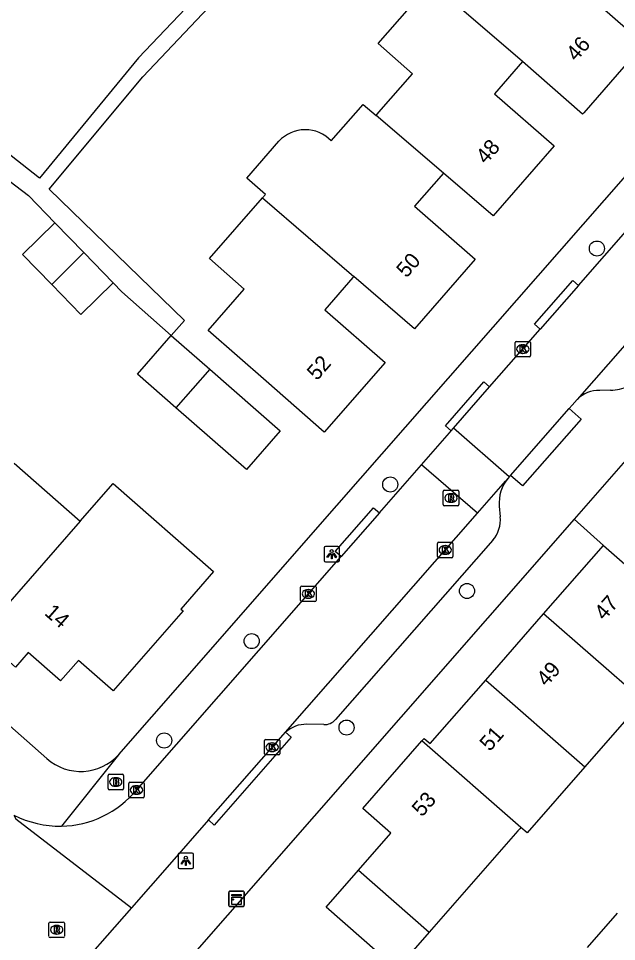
# Model space of a CAD drawing. Extents: x 158474 to 159560, y 388525 to 389605.
# Drawn here: x 158756.5 to 158795.3, y 388856.6 to 388916.5 of the extents above; entities that cross this region are included whole.
import ezdxf

# ---------------------------------------------------------------- set-up
doc = ezdxf.new("R2010")
doc.units = 0
for name, color, linetype in [('IMGEO_Boom', 7, 'Continuous'), ('IMGEO_Brandkraan', 7, 'Continuous'), ('IMGEO_Kast', 7, 'Continuous'), ('IMGEO_Kolk', 7, 'Continuous'), ('IMGEO_Lichtpunt', 7, 'Continuous'), ('IMGEO_Pand', 7, 'Continuous'), ('IMGEO_Pand_nummerreeks', 7, 'Continuous'), ('IMGEO_Rijbaan_lokaal_open', 7, 'Continuous'), ('IMGEO_Rioolput', 7, 'Continuous'), ('IMGEO_Voetpad_open', 7, 'Continuous')]:
    doc.layers.add(name, color=color, linetype=linetype)

msp = doc.modelspace()

# ---------------------------------------------------------------- linework, layer by layer
at = {"layer": 'IMGEO_Boom'}
for centre in [(158793.979, 388901.55), (158780.575, 388886.259), (158785.553, 388879.36), (158771.587, 388876.112), (158777.739, 388870.505), (158765.91, 388869.67)]:
    msp.add_circle(centre, 0.489, dxfattribs=at)
at = {"layer": 'IMGEO_Brandkraan'}
for p, q in [((158762.27, 388866.554), (158762.27, 388867.406)), ((158762.345, 388867.48), (158763.197, 388867.48)), ((158762.758, 388867.26), (158762.783, 388867.26)), ((158763.271, 388867.406), (158763.271, 388866.554)), ((158762.781, 388866.7), (158762.756, 388866.7)), ((158763.197, 388866.48), (158762.345, 388866.48))]:
    msp.add_line(p, q, dxfattribs=at)
for points in [[(158762.27, 388866.554), (158762.27, 388867.406)], [(158762.345, 388867.48), (158763.197, 388867.48)], [(158763.271, 388867.406), (158763.271, 388866.554)], [(158762.618, 388867.18), (158762.618, 388866.78), (158762.831, 388866.78)], [(158762.849, 388867.18), (158762.618, 388867.18)], [(158762.797, 388867.099), (158762.743, 388867.099), (158762.743, 388867.023)], [(158762.743, 388867.023), (158762.796, 388867.023)], [(158762.805, 388866.947), (158762.743, 388866.947), (158762.743, 388866.866)], [(158762.743, 388866.866), (158762.805, 388866.866)], [(158763.197, 388866.48), (158762.345, 388866.48)]]:
    msp.add_lwpolyline(points, dxfattribs=at)
for centre, radius, start, end in [((158762.347, 388867.404), 0.0765, 91.55205, 178.44795), ((158762.347, 388867.404), 0.0765, 91.55205, 178.44795), ((158763.195, 388867.404), 0.0765, 1.55205, 88.44795), ((158763.195, 388867.404), 0.0765, 1.55205, 88.44795), ((158762.798, 388867.061), 0.0379, 267.82845, 90.93552), ((158762.806, 388866.906), 0.0404, 269.87594, 90.50774), ((158762.837, 388867.031), 0.251, 268.66757, 293.53466), ((158762.853, 388867.035), 0.145, 59.4692, 91.53667), ((158762.878, 388867.082), 0.0922, 285.51372, 58.15012), ((158762.883, 388866.89), 0.105, 301.31148, 78.98903), ((158762.347, 388866.556), 0.0765, 181.55205, 268.44795), ((158762.347, 388866.556), 0.0765, 181.55205, 268.44795), ((158763.195, 388866.556), 0.0765, 271.55205, 358.44795), ((158763.195, 388866.556), 0.0765, 271.55205, 358.44795)]:
    msp.add_arc(centre, radius, start, end, dxfattribs=at)
for centre, major_axis, ratio, start_param, end_param in [((158762.757, 388866.98), (-0.387, 0.002), 0.722429, 4.712389, 7.853982), ((158762.782, 388866.98), (-0.39, 0.002), 0.717154, 1.570796, 4.712389)]:
    msp.add_ellipse(centre, major_axis=major_axis, ratio=ratio, start_param=start_param, end_param=end_param, dxfattribs=at)
at = {"layer": 'IMGEO_Kast'}
for p, q in [((158770.1, 388858.98), (158770.1, 388859.821)), ((158770.1, 388859.821), (158770.1, 388858.98)), ((158770.175, 388859.905), (158771.016, 388859.905)), ((158771.016, 388859.905), (158770.175, 388859.905)), ((158771.1, 388859.83), (158771.1, 388858.989)), ((158771.1, 388858.989), (158771.1, 388859.83)), ((158771.025, 388858.905), (158770.184, 388858.905)), ((158770.184, 388858.905), (158771.025, 388858.905))]:
    msp.add_line(p, q, dxfattribs=at)
for points in [[(158770.295, 388859.695), (158770.895, 388859.695), (158770.895, 388859.61), (158770.295, 388859.61), (158770.295, 388859.695)], [(158770.295, 388859.52), (158770.895, 388859.52), (158770.895, 388859.031), (158770.295, 388859.031), (158770.295, 388859.52)]]:
    msp.add_lwpolyline(points, dxfattribs=at)
msp.add_circle((158770.379, 388859.369), 0.0377, dxfattribs=at)
for centre, start, end in [((158770.178, 388859.827), 92.4484, 184.28452), ((158770.178, 388859.827), 92.4484, 184.28452), ((158771.022, 388859.827), 2.4484, 94.28452), ((158771.022, 388859.827), 2.4484, 94.28452), ((158770.178, 388858.983), 182.4484, 274.28452), ((158770.178, 388858.983), 182.4484, 274.28452), ((158771.022, 388858.983), 272.4484, 4.28452), ((158771.022, 388858.983), 272.4484, 4.28452)]:
    msp.add_arc(centre, 0.0779, start, end, dxfattribs=at)
at = {"layer": 'IMGEO_Kolk'}
for p, q in [((158788.674, 388894.609), (158788.674, 388895.461)), ((158788.749, 388895.535), (158789.601, 388895.535)), ((158789.675, 388895.461), (158789.675, 388894.609)), ((158789.185, 388894.755), (158789.16, 388894.755)), ((158789.162, 388895.315), (158789.187, 388895.315)), ((158789.601, 388894.535), (158788.749, 388894.535)), ((158783.64, 388881.591), (158783.64, 388882.443)), ((158783.715, 388882.517), (158784.567, 388882.517)), ((158784.128, 388882.297), (158784.153, 388882.297)), ((158784.641, 388882.443), (158784.641, 388881.591)), ((158784.151, 388881.737), (158784.126, 388881.737)), ((158784.567, 388881.517), (158783.715, 388881.517)), ((158774.761, 388878.747), (158774.761, 388879.599)), ((158774.836, 388879.673), (158775.688, 388879.673)), ((158775.249, 388879.453), (158775.274, 388879.453)), ((158775.762, 388879.599), (158775.762, 388878.747)), ((158775.688, 388878.673), (158774.836, 388878.673)), ((158775.272, 388878.893), (158775.247, 388878.893)), ((158772.413, 388868.807), (158772.413, 388869.659)), ((158772.488, 388869.733), (158773.34, 388869.733)), ((158773.414, 388869.659), (158773.414, 388868.807)), ((158772.901, 388869.513), (158772.926, 388869.513)), ((158773.34, 388868.733), (158772.488, 388868.733)), ((158772.924, 388868.953), (158772.899, 388868.953)), ((158763.613, 388866.036), (158763.613, 388866.888)), ((158763.688, 388866.962), (158764.54, 388866.962)), ((158764.101, 388866.742), (158764.126, 388866.742)), ((158764.614, 388866.888), (158764.614, 388866.036)), ((158764.124, 388866.182), (158764.099, 388866.182)), ((158764.54, 388865.962), (158763.688, 388865.962))]:
    msp.add_line(p, q, dxfattribs=at)
for points in [[(158788.674, 388894.609), (158788.674, 388895.461)], [(158788.749, 388895.535), (158789.601, 388895.535)], [(158789.675, 388895.461), (158789.675, 388894.609)], [(158788.995, 388895.235), (158789.118, 388895.235), (158789.118, 388895.084), (158789.248, 388895.235), (158789.412, 388895.235), (158789.266, 388895.084), (158789.419, 388894.835), (158789.267, 388894.835), (158789.182, 388894.999), (158789.118, 388894.932), (158789.118, 388894.835), (158788.995, 388894.835), (158788.995, 388895.235)], [(158789.601, 388894.535), (158788.749, 388894.535)], [(158783.64, 388881.591), (158783.64, 388882.443)], [(158783.715, 388882.517), (158784.567, 388882.517)], [(158783.961, 388882.217), (158784.084, 388882.217), (158784.084, 388882.066), (158784.214, 388882.217), (158784.378, 388882.217), (158784.232, 388882.066), (158784.385, 388881.817), (158784.233, 388881.817), (158784.148, 388881.981), (158784.084, 388881.914), (158784.084, 388881.817), (158783.961, 388881.817), (158783.961, 388882.217)], [(158784.641, 388882.443), (158784.641, 388881.591)], [(158784.567, 388881.517), (158783.715, 388881.517)], [(158774.761, 388878.747), (158774.761, 388879.599)], [(158774.836, 388879.673), (158775.688, 388879.673)], [(158775.082, 388879.373), (158775.205, 388879.373), (158775.205, 388879.222), (158775.335, 388879.373), (158775.499, 388879.373), (158775.353, 388879.222), (158775.506, 388878.973), (158775.354, 388878.973), (158775.269, 388879.137), (158775.205, 388879.07), (158775.205, 388878.973), (158775.082, 388878.973), (158775.082, 388879.373)], [(158775.762, 388879.599), (158775.762, 388878.747)], [(158775.688, 388878.673), (158774.836, 388878.673)], [(158772.413, 388868.807), (158772.413, 388869.659)], [(158772.488, 388869.733), (158773.34, 388869.733)], [(158773.414, 388869.659), (158773.414, 388868.807)], [(158772.734, 388869.433), (158772.857, 388869.433), (158772.857, 388869.282), (158772.987, 388869.433), (158773.151, 388869.433), (158773.005, 388869.282), (158773.158, 388869.033), (158773.006, 388869.033), (158772.921, 388869.197), (158772.857, 388869.13), (158772.857, 388869.033), (158772.734, 388869.033), (158772.734, 388869.433)], [(158773.34, 388868.733), (158772.488, 388868.733)], [(158763.613, 388866.036), (158763.613, 388866.888)], [(158763.688, 388866.962), (158764.54, 388866.962)], [(158763.934, 388866.662), (158764.057, 388866.662), (158764.057, 388866.511), (158764.187, 388866.662), (158764.351, 388866.662), (158764.205, 388866.511), (158764.358, 388866.262), (158764.206, 388866.262), (158764.121, 388866.426), (158764.057, 388866.359), (158764.057, 388866.262), (158763.934, 388866.262), (158763.934, 388866.662)], [(158764.614, 388866.888), (158764.614, 388866.036)], [(158764.54, 388865.962), (158763.688, 388865.962)]]:
    msp.add_lwpolyline(points, dxfattribs=at)
for centre, start, end in [((158788.751, 388895.459), 91.55205, 178.44795), ((158788.751, 388895.459), 91.55205, 178.44795), ((158789.599, 388895.459), 1.55205, 88.44795), ((158789.599, 388895.459), 1.55205, 88.44795), ((158788.751, 388894.611), 181.55205, 268.44795), ((158788.751, 388894.611), 181.55205, 268.44795), ((158789.599, 388894.611), 271.55205, 358.44795), ((158789.599, 388894.611), 271.55205, 358.44795), ((158783.717, 388882.441), 91.55205, 178.44795), ((158783.717, 388882.441), 91.55205, 178.44795), ((158784.565, 388882.441), 1.55205, 88.44795), ((158784.565, 388882.441), 1.55205, 88.44795), ((158783.717, 388881.593), 181.55205, 268.44795), ((158783.717, 388881.593), 181.55205, 268.44795), ((158784.565, 388881.593), 271.55205, 358.44795), ((158784.565, 388881.593), 271.55205, 358.44795), ((158774.838, 388879.597), 91.55205, 178.44795), ((158774.838, 388879.597), 91.55205, 178.44795), ((158775.686, 388879.597), 1.55205, 88.44795), ((158775.686, 388879.597), 1.55205, 88.44795), ((158774.838, 388878.749), 181.55205, 268.44795), ((158774.838, 388878.749), 181.55205, 268.44795), ((158775.686, 388878.749), 271.55205, 358.44795), ((158775.686, 388878.749), 271.55205, 358.44795), ((158772.49, 388869.657), 91.55205, 178.44795), ((158772.49, 388869.657), 91.55205, 178.44795), ((158773.338, 388869.657), 1.55205, 88.44795), ((158773.338, 388869.657), 1.55205, 88.44795), ((158772.49, 388868.809), 181.55205, 268.44795), ((158772.49, 388868.809), 181.55205, 268.44795), ((158773.338, 388868.809), 271.55205, 358.44795), ((158773.338, 388868.809), 271.55205, 358.44795), ((158763.69, 388866.886), 91.55205, 178.44795), ((158763.69, 388866.886), 91.55205, 178.44795), ((158764.538, 388866.886), 1.55205, 88.44795), ((158764.538, 388866.886), 1.55205, 88.44795), ((158763.69, 388866.038), 181.55205, 268.44795), ((158763.69, 388866.038), 181.55205, 268.44795), ((158764.538, 388866.038), 271.55205, 358.44795), ((158764.538, 388866.038), 271.55205, 358.44795)]:
    msp.add_arc(centre, 0.0765, start, end, dxfattribs=at)
for centre, major_axis, ratio, start_param, end_param in [((158789.161, 388895.035), (-0.387, 0.002), 0.722429, 4.712389, 7.853982), ((158789.186, 388895.035), (-0.39, 0.002), 0.717154, 1.570796, 4.712389), ((158784.127, 388882.017), (-0.387, 0.002), 0.722429, 4.712389, 7.853982), ((158784.152, 388882.017), (-0.39, 0.002), 0.717154, 1.570796, 4.712389), ((158775.248, 388879.173), (-0.387, 0.002), 0.722429, 4.712389, 7.853982), ((158775.273, 388879.173), (-0.39, 0.002), 0.717154, 1.570796, 4.712389), ((158772.9, 388869.233), (-0.387, 0.002), 0.722429, 4.712389, 7.853982), ((158772.925, 388869.233), (-0.39, 0.002), 0.717154, 1.570796, 4.712389), ((158764.1, 388866.462), (-0.387, 0.002), 0.722429, 4.712389, 7.853982), ((158764.125, 388866.462), (-0.39, 0.002), 0.717154, 1.570796, 4.712389)]:
    msp.add_ellipse(centre, major_axis=major_axis, ratio=ratio, start_param=start_param, end_param=end_param, dxfattribs=at)
at = {"layer": 'IMGEO_Lichtpunt'}
for p, q in [((158777.182, 388882.239), (158776.374, 388882.239)), ((158777.182, 388882.239), (158776.374, 388882.239)), ((158776.28, 388882.144), (158776.28, 388881.337)), ((158776.28, 388882.144), (158776.28, 388881.337)), ((158777.276, 388881.337), (158777.276, 388882.144)), ((158777.276, 388881.337), (158777.276, 388882.144)), ((158776.374, 388881.243), (158777.182, 388881.243)), ((158776.374, 388881.243), (158777.182, 388881.243)), ((158766.817, 388862.274), (158766.817, 388861.467)), ((158766.817, 388862.274), (158766.817, 388861.467)), ((158767.719, 388862.369), (158766.911, 388862.369)), ((158767.719, 388862.369), (158766.911, 388862.369)), ((158767.813, 388861.467), (158767.813, 388862.274)), ((158767.813, 388861.467), (158767.813, 388862.274)), ((158766.911, 388861.373), (158767.719, 388861.373)), ((158766.911, 388861.373), (158767.719, 388861.373))]:
    msp.add_line(p, q, dxfattribs=at)
for points in [[(158776.654, 388881.808), (158776.693, 388881.78), (158776.505, 388881.518), (158776.467, 388881.545), (158776.654, 388881.808)], [(158776.756, 388881.76), (158776.803, 388881.76), (158776.803, 388881.438), (158776.756, 388881.438), (158776.756, 388881.76)], [(158776.866, 388881.78), (158776.904, 388881.807), (158777.091, 388881.545), (158777.052, 388881.517), (158776.866, 388881.78)], [(158767.191, 388861.938), (158767.23, 388861.91), (158767.042, 388861.648), (158767.004, 388861.675), (158767.191, 388861.938)], [(158767.293, 388861.89), (158767.34, 388861.89), (158767.34, 388861.568), (158767.293, 388861.568), (158767.293, 388861.89)], [(158767.403, 388861.91), (158767.441, 388861.937), (158767.628, 388861.675), (158767.589, 388861.647), (158767.403, 388861.91)]]:
    msp.add_lwpolyline(points, dxfattribs=at)
for centre in [(158776.779, 388881.942), (158767.316, 388862.072)]:
    msp.add_circle(centre, 0.0994, dxfattribs=at)
for centre, start, end in [((158776.374, 388882.144), 90, 180), ((158776.374, 388882.144), 90, 180), ((158777.182, 388882.144), 0, 90), ((158777.182, 388882.144), 0, 90), ((158776.374, 388881.337), 180, 270), ((158776.374, 388881.337), 180, 270), ((158777.182, 388881.337), 270, 0), ((158777.182, 388881.337), 270, 360), ((158766.911, 388862.274), 90, 180), ((158766.911, 388862.274), 90, 180), ((158767.719, 388862.274), 0, 90), ((158767.719, 388862.274), 0, 90), ((158766.911, 388861.467), 180, 270), ((158766.911, 388861.467), 180, 270), ((158767.719, 388861.467), 270, 0), ((158767.719, 388861.467), 270, 360)]:
    msp.add_arc(centre, 0.0946, start, end, dxfattribs=at)
at = {"layer": 'IMGEO_Pand'}
for points in [[(158795.023, 388920.378), (158793.138, 388918.224), (158797.03, 388914.824), (158793.12, 388910.355), (158793.044, 388910.268), (158789.16, 388913.666)], [(158779.654, 388910.181), (158779.839, 388910.393), (158782.017, 388912.883), (158779.787, 388914.833), (158783.238, 388918.777)], [(158789.16, 388913.666), (158783.238, 388918.777)], [(158789.16, 388913.666), (158787.338, 388911.582), (158791.208, 388908.196), (158787.256, 388903.678), (158784.034, 388906.434)], [(158776.749, 388908.527), (158778.82, 388910.894), (158779.654, 388910.181)], [(158784.034, 388906.434), (158779.654, 388910.181)], [(158772.29, 388904.84), (158772.48, 388905.057), (158771.265, 388906.12), (158773.352, 388908.505)], [(158784.034, 388906.434), (158782.155, 388904.287), (158786.077, 388900.856), (158782.138, 388896.353), (158778.212, 388899.737)], [(158778.212, 388899.737), (158778.155, 388899.672), (158776.329, 388897.585), (158780.238, 388894.166), (158776.294, 388889.657), (158772.53, 388892.949), (158768.762, 388896.246), (158771.101, 388898.919), (158768.84, 388900.897), (158772.29, 388904.84)], [(158772.29, 388904.84), (158778.212, 388899.737)], [(158758.622, 388899.212), (158756.714, 388901.173), (158758.815, 388903.218)], [(158758.815, 388903.218), (158760.689, 388901.293)], [(158758.622, 388899.212), (158760.689, 388901.293)], [(158760.689, 388901.293), (158762.609, 388899.321)], [(158762.609, 388899.321), (158760.508, 388897.275), (158758.622, 388899.212)], [(158766.672, 388891.227), (158764.177, 388893.41), (158766.367, 388895.914)], [(158766.367, 388895.914), (158768.869, 388893.726)], [(158768.869, 388893.726), (158773.431, 388889.734), (158771.241, 388887.23), (158766.672, 388891.227)], [(158768.869, 388893.726), (158766.672, 388891.227)], [(158756.172, 388887.648), (158760.466, 388883.892)], [(158760.466, 388883.892), (158762.593, 388886.316), (158769.113, 388880.614), (158766.99, 388878.186), (158767.132, 388878.062), (158762.602, 388872.883), (158760.344, 388874.858), (158759.194, 388873.543), (158757.098, 388875.376), (158756.267, 388874.425), (158753.943, 388876.458)], [(158760.466, 388883.892), (158753.943, 388876.458)], [(158790.519, 388877.871), (158794.414, 388882.316)], [(158794.414, 388882.316), (158800.837, 388876.689)], [(158786.764, 388873.586), (158790.519, 388877.871)], [(158796.948, 388872.251), (158790.519, 388877.871)], [(158782.625, 388869.639), (158782.772, 388869.807), (158783.158, 388869.47), (158786.764, 388873.586)], [(158786.764, 388873.586), (158793.194, 388867.966)], [(158796.948, 388872.251), (158793.194, 388867.966)], [(158778.517, 388861.261), (158780.621, 388863.662), (158778.792, 388865.264), (158782.625, 388869.639)], [(158789.053, 388864.037), (158782.625, 388869.639)], [(158793.194, 388867.966), (158789.449, 388863.692), (158789.053, 388864.037)], [(158789.053, 388864.037), (158788.971, 388863.943), (158788.856, 388863.812), (158783.101, 388857.244)], [(158783.101, 388857.244), (158780.998, 388854.843), (158776.413, 388858.86), (158778.517, 388861.261)], [(158778.517, 388861.261), (158783.101, 388857.244)], [(158793.361, 388856.252), (158795.318, 388858.486)]]:
    msp.add_lwpolyline(points, dxfattribs=at)
msp.add_arc((158775.061, 388906.921), 2.33, 43.57153, 137.17059, dxfattribs=at)
at = {"layer": 'IMGEO_Rijbaan_lokaal_open'}
for points in [[(158818.213, 388920.836), (158792.7, 388891.773)], [(158792.786, 388899.152), (158796.16, 388902.998)], [(158792.786, 388899.152), (158790.3, 388896.317)], [(158787.022, 388892.58), (158790.3, 388896.317)], [(158784.684, 388889.914), (158787.022, 388892.58)], [(158792.7, 388891.773), (158792.369, 388891.396), (158792.181, 388891.181)], [(158788.381, 388886.851), (158792.181, 388891.181)], [(158782.604, 388887.543), (158784.415, 388889.608), (158784.535, 388889.744)], [(158784.535, 388889.744), (158784.684, 388889.914)], [(158788.291, 388886.749), (158784.684, 388889.914)], [(158795.826, 388887.817), (158792.495, 388884.015)], [(158779.873, 388884.428), (158782.604, 388887.543)], [(158786.227, 388884.396), (158782.604, 388887.543)], [(158786.227, 388884.396), (158788.058, 388886.484), (158788.228, 388886.677)], [(158788.291, 388886.749), (158788.228, 388886.677)], [(158788.381, 388886.851), (158788.291, 388886.749)], [(158773.778, 388870.206), (158786.227, 388884.396)], [(158779.873, 388884.428), (158777.383, 388881.589)], [(158794.414, 388882.316), (158792.495, 388884.015)], [(158764.112, 388866.459), (158777.383, 388881.589)], [(158768.777, 388864.518), (158773.623, 388870.039), (158773.778, 388870.206)], [(158756.168, 388864.834), (158756.279, 388864.585), (158763.786, 388858.832)], [(158768.777, 388864.518), (158766.25, 388861.639), (158763.786, 388858.832)], [(158763.786, 388858.832), (158759.531, 388853.985)]]:
    msp.add_lwpolyline(points, dxfattribs=at)
for centre, radius, start, end in [((158759.127, 388870.599), 6.48, 271.03415, 320.293), ((158759.129, 388870.608), 6.489, 242.84866, 271.01523)]:
    msp.add_arc(centre, radius, start, end, dxfattribs=at)
at = {"layer": 'IMGEO_Rioolput'}
for p, q in [((158784.013, 388884.958), (158784.013, 388885.81)), ((158784.088, 388885.884), (158784.94, 388885.884)), ((158785.014, 388885.81), (158785.014, 388884.958)), ((158784.501, 388885.664), (158784.526, 388885.664)), ((158784.94, 388884.884), (158784.088, 388884.884)), ((158784.524, 388885.104), (158784.499, 388885.104)), ((158758.437, 388856.978), (158758.437, 388857.83)), ((158758.512, 388857.904), (158759.364, 388857.904)), ((158758.925, 388857.684), (158758.95, 388857.684)), ((158759.438, 388857.83), (158759.438, 388856.978)), ((158758.948, 388857.124), (158758.923, 388857.124)), ((158759.364, 388856.904), (158758.512, 388856.904))]:
    msp.add_line(p, q, dxfattribs=at)
for points in [[(158784.013, 388884.958), (158784.013, 388885.81)], [(158784.088, 388885.884), (158784.94, 388885.884)], [(158785.014, 388885.81), (158785.014, 388884.958)], [(158784.602, 388885.582), (158784.35, 388885.584), (158784.35, 388885.184)], [(158784.35, 388885.184), (158784.474, 388885.184), (158784.474, 388885.346), (158784.485, 388885.346)], [(158784.528, 388885.503), (158784.474, 388885.503), (158784.474, 388885.422)], [(158784.474, 388885.422), (158784.526, 388885.422)], [(158784.532, 388885.317), (158784.603, 388885.184), (158784.743, 388885.184), (158784.678, 388885.31)], [(158784.94, 388884.884), (158784.088, 388884.884)], [(158758.437, 388856.978), (158758.437, 388857.83)], [(158758.512, 388857.904), (158759.364, 388857.904)], [(158759.438, 388857.83), (158759.438, 388856.978)], [(158759.026, 388857.602), (158758.774, 388857.604), (158758.774, 388857.204)], [(158758.774, 388857.204), (158758.898, 388857.204), (158758.898, 388857.366), (158758.909, 388857.366)], [(158758.952, 388857.523), (158758.898, 388857.523), (158758.898, 388857.442)], [(158758.898, 388857.442), (158758.95, 388857.442)], [(158758.956, 388857.337), (158759.027, 388857.204), (158759.167, 388857.204), (158759.102, 388857.33)], [(158759.364, 388856.904), (158758.512, 388856.904)]]:
    msp.add_lwpolyline(points, dxfattribs=at)
for centre, radius, start, end in [((158784.09, 388885.808), 0.0765, 91.55205, 178.44795), ((158784.09, 388885.808), 0.0765, 91.55205, 178.44795), ((158784.938, 388885.808), 0.0765, 1.55205, 88.44795), ((158784.938, 388885.808), 0.0765, 1.55205, 88.44795), ((158784.484, 388885.293), 0.0533, 26.02933, 88.69889), ((158784.51, 388885.611), 0.19, 274.7715, 282.96867), ((158784.534, 388885.407), 0.0964, 77.00612, 93.18647), ((158784.548, 388885.464), 0.0378, 276.66336, 79.67722), ((158784.601, 388885.472), 0.109, 350.36119, 89.41601), ((158784.599, 388885.472), 0.112, 277.58423, 350.98172), ((158784.583, 388885.257), 0.108, 29.51342, 73.79051), ((158784.09, 388884.96), 0.0765, 181.55205, 268.44795), ((158784.09, 388884.96), 0.0765, 181.55205, 268.44795), ((158784.938, 388884.96), 0.0765, 271.55205, 358.44795), ((158784.938, 388884.96), 0.0765, 271.55205, 358.44795), ((158758.514, 388857.828), 0.0765, 91.55205, 178.44795), ((158758.514, 388857.828), 0.0765, 91.55205, 178.44795), ((158759.362, 388857.828), 0.0765, 1.55205, 88.44795), ((158759.362, 388857.828), 0.0765, 1.55205, 88.44795), ((158758.908, 388857.313), 0.0533, 26.02933, 88.69889), ((158758.934, 388857.631), 0.19, 274.7715, 282.96867), ((158758.958, 388857.427), 0.0964, 77.00612, 93.18647), ((158758.972, 388857.484), 0.0378, 276.66336, 79.67722), ((158759.025, 388857.492), 0.109, 350.36119, 89.41601), ((158759.023, 388857.492), 0.112, 277.58423, 350.98172), ((158759.007, 388857.277), 0.108, 29.51342, 73.79051), ((158758.514, 388856.98), 0.0765, 181.55205, 268.44795), ((158758.514, 388856.98), 0.0765, 181.55205, 268.44795), ((158759.362, 388856.98), 0.0765, 271.55205, 358.44795), ((158759.362, 388856.98), 0.0765, 271.55205, 358.44795)]:
    msp.add_arc(centre, radius, start, end, dxfattribs=at)
for centre, major_axis, ratio, start_param, end_param in [((158784.5, 388885.384), (-0.387, 0.002), 0.722429, 4.712389, 7.853982), ((158784.525, 388885.384), (-0.39, 0.002), 0.717154, 1.570796, 4.712389), ((158758.924, 388857.404), (-0.387, 0.002), 0.722429, 4.712389, 7.853982), ((158758.949, 388857.404), (-0.39, 0.002), 0.717154, 1.570796, 4.712389)]:
    msp.add_ellipse(centre, major_axis=major_axis, ratio=ratio, start_param=start_param, end_param=end_param, dxfattribs=at)
at = {"layer": 'IMGEO_Voetpad_open'}
for points in [[(158762.962, 388868.767), (158769.386, 388876.091), (158775.72, 388883.311), (158826.285, 388940.957)], [(158766.367, 388895.914), (158767.225, 388896.883), (158758.448, 388905.394), (158764.522, 388912.676), (158770.311, 388918.809), (158776.108, 388925.599), (158775.159, 388926.41), (158768.586, 388918.48), (158764.239, 388913.913), (158757.828, 388906.105), (158748.824, 388913.185)], [(158747.221, 388912.501), (158757.101, 388904.979), (158758.815, 388903.218)], [(158721.088, 388901.308), (158758.299, 388868.499)], [(158762.609, 388899.321), (158763.163, 388898.752), (158766.367, 388895.914)], [(158790.3, 388896.317), (158789.921, 388896.642), (158792.407, 388899.477), (158792.786, 388899.152)], [(158784.535, 388889.744), (158784.157, 388890.07), (158786.644, 388892.906), (158787.022, 388892.58)], [(158794.86, 388892.379), (158794.164, 388892.36)], [(158792.181, 388891.181), (158792.963, 388890.495), (158789.163, 388886.165), (158788.381, 388886.851)], [(158777.383, 388881.589), (158777.005, 388881.915), (158779.495, 388884.754), (158779.873, 388884.428)], [(158787.644, 388884.854), (158787.713, 388884.168)], [(158792.495, 388884.015), (158770.012, 388858.352), (158763.289, 388850.678)], [(158787.226, 388882.649), (158777.031, 388871.036)], [(158773.778, 388870.206), (158774.152, 388869.884), (158769.155, 388864.192), (158768.777, 388864.518)], [(158776.258, 388870.696), (158775.169, 388870.719)], [(158762.962, 388868.767), (158762.869, 388868.63), (158759.244, 388864.12)]]:
    msp.add_lwpolyline(points, dxfattribs=at)
for centre, radius, start, end in [((158794.124, 388890.34), 2.02, 88.87086, 134.82639), ((158794.896, 388894.742), 2.363, 269.11868, 298.08392), ((158790.154, 388885.055), 2.519, 139.90112, 184.57305), ((158785.717, 388883.97), 2.006, 318.79254, 5.65517), ((158776.277, 388871.702), 1.006, 268.92389, 318.56019), ((158775.123, 388868.702), 2.018, 88.69045, 131.79744), ((158760.496, 388870.974), 3.309, 228.40397, 318.1748)]:
    msp.add_arc(centre, radius, start, end, dxfattribs=at)

# ---------------------------------------------------------------- texts
at = {"layer": 'IMGEO_Pand_nummerreeks'}
for s, rotation, p in [('46', 48.8168, (158792.634, 388913.627)), ('48', 48.82173, (158786.778, 388906.96)), ('50', 48.82173, (158781.628, 388899.598)), ('52', 48.82173, (158775.823, 388892.947)), ('47', 48.77431, (158794.46, 388877.393)), ('14', 318.82725, (158758.091, 388877.856)), ('49', 48.77431, (158790.708, 388873.111)), ('51', 48.7759, (158787.031, 388868.914)), ('53', 48.7759, (158782.632, 388864.669))]:
    msp.add_text(s, height=1, rotation=rotation, dxfattribs=at).set_placement(p)

doc.saveas('drawing.dxf')
